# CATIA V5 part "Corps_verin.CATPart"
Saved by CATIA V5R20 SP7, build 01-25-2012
Part number: Corps_verin
Bounding box of the stored display mesh (mm): x -200.608 to 200.608, y -18.904 to 32.357, z 12.893 to 81.378
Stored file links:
  F:\Travaux\Modélisations\CFAO_2011\MMS\MMS_GR2\AA_OK\tquattrone\Catia\Corps_verin.CATPart
  C:\Users\Tom\Documents\Cours 2A\CFAO\Projet thinkmotion\Aileron_citroen.CATProduct
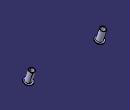
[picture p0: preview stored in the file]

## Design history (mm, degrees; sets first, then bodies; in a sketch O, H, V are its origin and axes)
Parameters
  rayon_int_verin = 10.75 mm
  epaisseur_corps_verin = 3 mm
Set1
  Plane1 "Plan_verin": linked copy from another document
  Plane2 "Plan_sym": linked copy from another document
Body1 (main body)
  Sketch1 on Plane1, origin (180, 0, 0), H (0, 1, 0), V (0, 0, 1)
    line L1 (10.9466, 15.9121) -> (29.6084, 73.9077)
    line L2 (29.6084, 73.9077) -> (32.4642, 72.9888)
    line L3 (32.4642, 72.9888) -> (14.7213, 17.849)
    line L4 (14.7213, 17.849) -> (21.2549, 15.7466)
    line L5 (21.2549, 15.7466) -> (20.336, 12.8908)
    line L6 (20.336, 12.8908) -> (10.9466, 15.9121)
    axis line L7 (31.0331, 113.4301) -> (-4.4211, 3.2485)
    distance L1 L7 = 10.75
    distance L1 L3 = 3 {= epaisseur_corps_verin}
    distance L4 L6 = 3 {= epaisseur_corps_verin}
    perpendicularity: L2 L1, L4 L3
    parallelism: L5 L3
  Shaft1: profile Sketch1, axis Sketch1.L7, angle 360
  Mirror1: of the body so far, about Plane2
